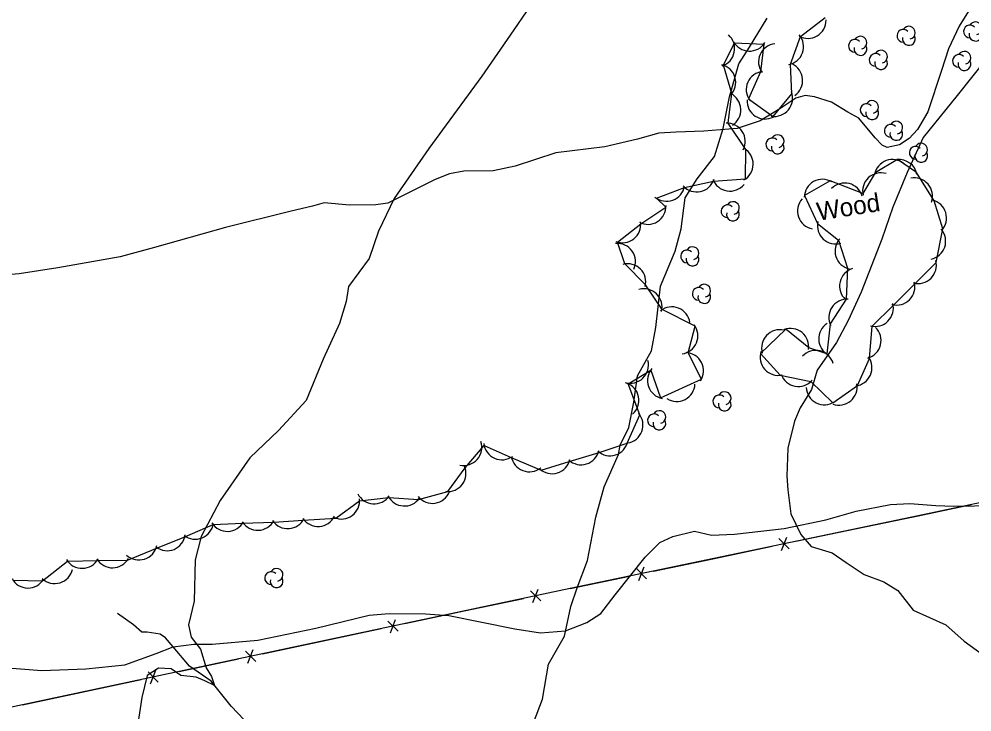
# Model space of a CAD drawing. Extents: x 643342 to 646936, y 5873857 to 5876103.
# Drawn here: x 645420.4 to 645577.3, y 5875713.3 to 5875827.4 of the extents above; entities that cross this region are included whole.
import ezdxf

# ---------------------------------------------------------------- set-up
doc = ezdxf.new("R2010")
doc.units = 0
for name, color, linetype in [('Niveau 2', 7, 'Continuous'), ('Niveau 22', 7, 'Continuous'), ('Niveau 37', 7, 'Continuous'), ('Niveau 4', 7, 'Continuous'), ('Niveau 44', 7, 'Continuous')]:
    doc.layers.add(name, color=color, linetype=linetype)

msp = doc.modelspace()

# ---------------------------------------------------------------- linework, layer by layer
at = {"layer": 'Niveau 2'}
for points in [[(645504.52, 5875829.46), (645501.28, 5875824.74), (645496.59, 5875817.97), (645487.87, 5875806.09), (645482.16, 5875797.83), (645479.59, 5875792.45), (645478.03, 5875787.96), (645474.65, 5875783.32), (645474.23, 5875780.85), (645473.18, 5875777.22), (645470.47, 5875771.36), (645467.68, 5875764.56), (645463.11, 5875759.64), (645458.39, 5875755.12), (645453.48, 5875748.08), (645450.38, 5875742.18), (645449.4, 5875738.32), (645449.2, 5875731.51), (645448.28, 5875727.6), (645448.75, 5875725.6), (645450.25, 5875723.58), (645451.22, 5875720.53), (645452.06, 5875719.12), (645452.59, 5875717.64), (645450.99, 5875718.4), (645449.53, 5875719), (645447.02, 5875719.28), (645445.42, 5875720.39), (645443.34, 5875720.45), (645441.49, 5875719.24), (645440.6, 5875715.62), (645439.95, 5875711.33)], [(645503.62, 5875707.59), (645506.6, 5875715.38), (645507.58, 5875721.14), (645510.21, 5875725.77), (645511.27, 5875730.61), (645512.31, 5875733.72), (645513.98, 5875738.2), (645515.35, 5875745.33), (645516.75, 5875750.32), (645519.08, 5875755.67), (645519.35, 5875757.2), (645520.81, 5875760.11), (645521.64, 5875764.29), (645522.23, 5875768.62), (645524.5, 5875772.76), (645525.25, 5875776.58), (645526.02, 5875783.37), (645528.43, 5875789.13), (645529.42, 5875792.81), (645530.05, 5875797.95), (645532.07, 5875801.08), (645534.9, 5875804.73), (645536.32, 5875809.37), (645537.35, 5875814.55), (645538.93, 5875820.01), (645540.69, 5875822.76), (645543.59, 5875827.52)], [(645580.21, 5875821.57), (645574.87, 5875814.77), (645569.25, 5875807.88), (645566.62, 5875802.11), (645564.26, 5875796.42), (645562.45, 5875791.13), (645559.05, 5875782.4), (645556.89, 5875777.71), (645554.98, 5875774.14), (645551.78, 5875769.53), (645550.86, 5875766.39), (645549.01, 5875763.34), (645548.06, 5875761.18), (645546.97, 5875756.69), (645546.81, 5875752.11), (645546.96, 5875749.87), (645547.48, 5875745.92), (645549.11, 5875742.48), (645550.83, 5875740.49), (645554.3, 5875739.46), (645556.57, 5875737.86), (645559.55, 5875735.92), (645562.81, 5875734.69), (645565.11, 5875733.27), (645567.64, 5875730.02), (645573.01, 5875727.59), (645576, 5875724.9), (645580.59, 5875721.6)]]:
    msp.add_lwpolyline(points, dxfattribs=at)
at = {"layer": 'Niveau 22'}
for points in [[(645577.57, 5875829.99), (645575.16, 5875826.21), (645573.44, 5875822.48), (645572.27, 5875818.91), (645570.01, 5875812.13), (645568.33, 5875809.22), (645566.97, 5875807.72), (645565.35, 5875806.65), (645563.32, 5875806.25), (645562.49, 5875806.64), (645561.35, 5875807.82), (645558.65, 5875811.06), (645556.84, 5875812.06), (645554.18, 5875813.69), (645551.34, 5875814.6), (645549.83, 5875814.82), (645548.27, 5875814.34), (645545.67, 5875812.62), (645542.41, 5875810.61), (645538.62, 5875809.36), (645533.15, 5875808.9), (645528.58, 5875808.74), (645525.72, 5875808.61), (645522.24, 5875807.63), (645516.84, 5875806.36), (645508.77, 5875805.33), (645502.07, 5875803.14), (645498.46, 5875802.37), (645493.63, 5875802.31), (645491.26, 5875801.87), (645488.92, 5875800.98), (645481.09, 5875797.07), (645479.16, 5875796.79), (645474.79, 5875796.76), (645470.61, 5875797.11), (645468.69, 5875796.59), (645465.2, 5875795.72), (645454.37, 5875793.06), (645442.67, 5875789.74), (645437.03, 5875788.22), (645426.8, 5875786.42), (645420.43, 5875785.41), (645414.01, 5875784.87)], [(645416.36, 5875720.7), (645424.15, 5875720.09), (645431.39, 5875720.37), (645437.8, 5875721.03), (645442.94, 5875722.87), (645445.76, 5875723.99), (645449.18, 5875724.4), (645452.18, 5875724.42), (645459.73, 5875725.07), (645469.23, 5875727.04), (645478.02, 5875729.19), (645481.33, 5875729.47), (645487.32, 5875729.41), (645491.14, 5875729.16), (645502.03, 5875726.96), (645506.23, 5875726.28), (645510.34, 5875726.63), (645513.9, 5875727.98), (645516.18, 5875729.45), (645518.54, 5875732.54), (645523.5, 5875738.76), (645525.92, 5875741.17), (645528.02, 5875742.16), (645531.61, 5875743.04), (645534.42, 5875742.36), (645538.19, 5875742.57), (645546.36, 5875743.5), (645553.23, 5875744.89), (645558.25, 5875746.36), (645563.88, 5875747.42), (645567.07, 5875747.58), (645571.34, 5875747.25), (645574.32, 5875747.16), (645581.18, 5875747.29)]]:
    msp.add_lwpolyline(points, dxfattribs=at)
at = {"layer": 'Niveau 37'}
for p, q in [((645656.81, 5875764.27), (645567.42, 5875745.36)), ((645567.42, 5875745.36), (645511.15, 5875733.6)), ((645511.15, 5875733.6), (645446.76, 5875719.92)), ((645446.76, 5875719.92), (645383.77, 5875706.55))]:
    msp.add_line(p, q, dxfattribs=at)
for points in [[(645567.42, 5875745.36), (645577.2, 5875747.43)], [(645558.09, 5875743.41), (645567.86, 5875745.45)], [(645548.31, 5875741.37), (645558.09, 5875743.41)], [(645545.52, 5875741.81), (645547.2, 5875740.11)], [(645545.93, 5875739.85), (645546.79, 5875742.07)], [(645534.62, 5875738.5), (645544.39, 5875740.55)], [(645524.84, 5875736.46), (645534.62, 5875738.5)], [(645522.05, 5875736.9), (645523.73, 5875735.21)], [(645522.46, 5875734.94), (645523.32, 5875737.17)], [(645511.15, 5875733.6), (645520.93, 5875735.64)], [(645504.6, 5875733.23), (645506.28, 5875731.54)], [(645505.01, 5875731.27), (645505.87, 5875733.5)], [(645493.7, 5875729.89), (645503.47, 5875731.97)], [(645483.92, 5875727.81), (645493.7, 5875729.89)], [(645481.13, 5875728.24), (645482.81, 5875726.56)], [(645481.54, 5875726.29), (645482.4, 5875728.51)], [(645470.23, 5875724.91), (645480.01, 5875726.98)], [(645460.45, 5875722.83), (645470.23, 5875724.91)], [(645457.66, 5875723.26), (645459.35, 5875721.57)], [(645458.07, 5875721.3), (645458.93, 5875723.53)], [(645446.76, 5875719.92), (645456.54, 5875722)], [(645441.63, 5875719.85), (645443.32, 5875718.17)], [(645442.04, 5875717.9), (645442.9, 5875720.12)], [(645430.72, 5875716.52), (645440.51, 5875718.59)], [(645420.94, 5875714.44), (645430.72, 5875716.52)]]:
    msp.add_lwpolyline(points, dxfattribs=at)
at = {"layer": 'Niveau 4'}
msp.add_lwpolyline([(645457.45, 5875711.96), (645455.29, 5875714.21), (645452.03, 5875718.35), (645448.47, 5875720.83), (645445.76, 5875723.99), (645444.48, 5875725.48), (645443.62, 5875726.1), (645441.51, 5875726.39), (645440.59, 5875726.43), (645439.21, 5875727.59), (645436.62, 5875729.46)], dxfattribs=at)
at = {"layer": 'Niveau 44'}
for points in [[(645537.13, 5875810.23), (645537.77, 5875815.12), (645536.4, 5875819.77), (645538.17, 5875823.45), (645543.02, 5875823.25), (645542.49, 5875818.69), (645540.52, 5875814.26), (645544.57, 5875811.35), (645547.66, 5875815.09), (645547.42, 5875819.97), (645549.04, 5875824.54), (645553.14, 5875827.65)], [(645419.4, 5875734.95), (645424.25, 5875734.86), (645428.38, 5875738.12), (645433.38, 5875738.2), (645438.23, 5875738.27), (645443.19, 5875740.27), (645447.68, 5875742.11), (645452.33, 5875744.15), (645457.18, 5875744.33), (645462.33, 5875744.52), (645467.18, 5875744.87), (645472.55, 5875745.18), (645476.46, 5875748.06), (645481.29, 5875748.59), (645486.14, 5875748.25), (645490.97, 5875749.55), (645493.84, 5875753.47), (645496.97, 5875757.17), (645501.4, 5875755.19), (645506.35, 5875753.1), (645510.99, 5875754.53), (645515.92, 5875756.01), (645520.53, 5875757.53), (645522.62, 5875762.18), (645520.71, 5875767.31), (645524.41, 5875769.57), (645526, 5875764.98), (645532.76, 5875768.09), (645530.55, 5875772.42), (645531.71, 5875776.79), (645526.27, 5875779.53), (645523.56, 5875783.62), (645520.12, 5875787.05), (645518.95, 5875790.66), (645522.76, 5875793.66), (645526.91, 5875796.4), (645525.34, 5875797.89), (645529.97, 5875799.67), (645534.72, 5875800.7), (645540, 5875801.05), (645540.07, 5875805.9), (645537.13, 5875810.23)], [(645550.42, 5875773.25), (645546.67, 5875776.33), (645542.47, 5875772.32), (645545.72, 5875768.72), (645550.76, 5875767.68), (645554.37, 5875764.19), (645558.47, 5875767.03), (645560.41, 5875771.48), (645560.87, 5875776.8), (645564.31, 5875780.22), (645567.96, 5875783.85), (645571.4, 5875787.28), (645572.5, 5875792.82), (645571.08, 5875797.46), (645568.17, 5875802.11), (645565.05, 5875804.24), (645561.33, 5875802.08), (645559.32, 5875798.66), (645553.95, 5875800.72), (645549.71, 5875798.35), (645551.88, 5875793.7), (645555.33, 5875790.96), (645556.79, 5875786.33), (645556.59, 5875781.24), (645553.92, 5875777.18), (645553.4, 5875772.22), (645550.42, 5875773.25)]]:
    msp.add_lwpolyline(points, dxfattribs=at)
for centre, radius, start, end in [((645550.28, 5875827.2), 3, 240.8205, 0.7984), ((645550.28, 5875827.2), 3, 240.8205, 0.7984), ((645550.28, 5875827.2), 3, 240.8205, 0.7984), ((645576.97, 5875825.33), 1.05, 44.1154, 269.804), ((645577.87, 5875825.86), 1.05, 282.2692, 149.7263), ((645535.22, 5875822.53), 3, 288.1566, 48.1346), ((645535.22, 5875822.53), 3, 288.1566, 48.1346), ((645535.22, 5875822.53), 3, 288.1566, 48.1346), ((645546.57, 5875822.84), 3, 280.5154, 40.4933), ((645546.57, 5875822.84), 3, 280.5154, 40.4933), ((645546.57, 5875822.84), 3, 280.5154, 40.4933), ((645566, 5875824.62), 1.05, 44.1154, 269.804), ((645566.9, 5875825.15), 1.05, 282.2692, 149.7263), ((645577.87, 5875824.81), 1.05, 166.9369, 29.6212), ((645540.67, 5875825.11), 3, 207.668, 327.6459), ((645540.67, 5875825.11), 3, 207.668, 327.6459), ((645540.67, 5875825.11), 3, 207.668, 327.6459), ((645545.15, 5875820.33), 3, 96.0461, 216.024), ((645545.15, 5875820.33), 3, 96.0461, 216.024), ((645545.15, 5875820.33), 3, 96.0461, 216.024), ((645558.03, 5875822.97), 1.05, 44.1154, 269.804), ((645558.93, 5875823.5), 1.05, 282.2692, 149.7263), ((645566.9, 5875824.1), 1.05, 166.9369, 29.6212), ((645558.93, 5875822.45), 1.05, 166.9369, 29.6212), ((645561.42, 5875820.66), 1.05, 44.1154, 269.804), ((645562.32, 5875821.19), 1.05, 282.2692, 149.7263), ((645576.05, 5875821.02), 1.05, 282.2692, 149.7263), ((645562.32, 5875820.14), 1.05, 166.9369, 29.6212), ((645575.15, 5875820.49), 1.05, 44.1154, 269.804), ((645576.05, 5875819.97), 1.05, 166.9369, 29.6212), ((645535.39, 5875816.95), 3, 316.3377, 76.3156), ((645535.39, 5875816.95), 3, 316.3377, 76.3156), ((645535.39, 5875816.95), 3, 316.3377, 76.3156), ((645543.12, 5875815.76), 3, 96.0461, 216.024), ((645543.12, 5875815.76), 3, 96.0461, 216.024), ((645543.12, 5875815.76), 3, 96.0461, 216.024), ((645546.42, 5875817.27), 3, 305.1398, 65.1177), ((645546.42, 5875817.27), 3, 305.1398, 65.1177), ((645546.42, 5875817.27), 3, 305.1398, 65.1177), ((645544.76, 5875814.35), 3, 260.3791, 20.3571), ((645544.76, 5875814.35), 3, 260.3791, 20.3571), ((645544.76, 5875814.35), 3, 260.3791, 20.3571), ((645536.24, 5875812.42), 3, 302.7735, 62.7515), ((645536.24, 5875812.42), 3, 302.7735, 62.7515), ((645536.24, 5875812.42), 3, 302.7735, 62.7515), ((645543.25, 5875813.92), 3, 177.1406, 297.1186), ((645543.25, 5875813.92), 3, 177.1406, 297.1186), ((645543.25, 5875813.92), 3, 177.1406, 297.1186), ((645560.86, 5875812.92), 1.05, 282.2692, 149.7263), ((645559.96, 5875812.39), 1.05, 44.1154, 269.804), ((645560.86, 5875811.87), 1.05, 166.9369, 29.6212), ((645536.96, 5875807.24), 3, 332.8523, 92.8302), ((645536.96, 5875807.24), 3, 332.8523, 92.8302), ((645536.96, 5875807.24), 3, 332.8523, 92.8302), ((645563.93, 5875808.98), 1.05, 44.1154, 269.804), ((645564.83, 5875809.51), 1.05, 282.2692, 149.7263), ((645544.41, 5875806.75), 1.05, 44.1154, 269.804), ((645545.31, 5875807.28), 1.05, 282.2692, 149.7263), ((645564.83, 5875808.46), 1.05, 166.9369, 29.6212), ((645538.27, 5875803.5), 3, 299.1809, 59.1588), ((645538.27, 5875803.5), 3, 299.1809, 59.1588), ((645538.27, 5875803.5), 3, 299.1809, 59.1588), ((645545.31, 5875806.23), 1.05, 166.9369, 29.6212), ((645568.03, 5875805.36), 1.05, 44.1154, 269.804), ((645568.93, 5875805.89), 1.05, 282.2692, 149.7263), ((645568.93, 5875804.84), 1.05, 166.9369, 29.6212), ((645564.21, 5875801.25), 3, 50.0669, 170.0449), ((645564.21, 5875801.25), 3, 50.0669, 170.0449), ((645564.21, 5875801.25), 3, 50.0669, 170.0449), ((645565.29, 5875801.25), 3, 10.616, 96.7417), ((645565.29, 5875801.25), 3, 10.616, 96.7417), ((645565.29, 5875801.25), 3, 10.616, 96.7417), ((645562.29, 5875799.05), 3, 73.3779, 193.3558), ((645562.29, 5875799.05), 3, 73.3779, 193.3558), ((645562.29, 5875799.05), 3, 73.3779, 193.3558), ((645567.8, 5875798.22), 3, 341.1335, 101.1114), ((645567.8, 5875798.22), 3, 341.1335, 101.1114), ((645567.8, 5875798.22), 3, 341.1335, 101.1114), ((645527, 5875800.38), 3, 230.2718, 350.2498), ((645527, 5875800.38), 3, 230.2718, 350.2498), ((645527, 5875800.38), 3, 230.2718, 350.2498), ((645531.97, 5875801.91), 3, 222.2419, 342.2198), ((645531.97, 5875801.91), 3, 222.2419, 342.2198), ((645531.97, 5875801.91), 3, 222.2419, 342.2198), ((645537.44, 5875802.05), 3, 200.7234, 320.7013), ((645537.44, 5875802.05), 3, 200.7234, 320.7013), ((645537.44, 5875802.05), 3, 200.7234, 320.7013), ((645552.69, 5875797.99), 3, 59.201, 179.179), ((645552.69, 5875797.99), 3, 59.201, 179.179), ((645552.69, 5875797.99), 3, 59.201, 179.179), ((645556.34, 5875797.38), 3, 15.9083, 135.8863), ((645556.34, 5875797.38), 3, 15.9083, 135.8863), ((645556.34, 5875797.38), 3, 15.9083, 135.8863), ((645523.92, 5875796.57), 3, 242.6115, 2.5895), ((645523.92, 5875796.57), 3, 242.6115, 2.5895), ((645523.92, 5875796.57), 3, 242.6115, 2.5895), ((645537.04, 5875795.73), 1.05, 44.1154, 269.804), ((645537.94, 5875796.26), 1.05, 282.2692, 149.7263), ((645551.58, 5875795.77), 3, 138.5965, 258.5744), ((645551.58, 5875795.77), 3, 138.5965, 258.5744), ((645551.58, 5875795.77), 3, 138.5965, 258.5744), ((645570.11, 5875794.62), 3, 317.0834, 77.0614), ((645570.11, 5875794.62), 3, 317.0834, 77.0614), ((645570.11, 5875794.62), 3, 317.0834, 77.0614), ((645537.94, 5875795.21), 1.05, 166.9369, 29.6212), ((645519.76, 5875793.55), 3, 248.1528, 8.1308), ((645519.76, 5875793.55), 3, 248.1528, 8.1308), ((645519.76, 5875793.55), 3, 248.1528, 8.1308), ((645554.85, 5875793.34), 3, 166.9551, 286.9331), ((645554.85, 5875793.34), 3, 166.9551, 286.9331), ((645554.85, 5875793.34), 3, 166.9551, 286.9331), ((645569.97, 5875790.8), 3, 281.1404, 41.1184), ((645569.97, 5875790.8), 3, 281.1404, 41.1184), ((645569.97, 5875790.8), 3, 281.1404, 41.1184), ((645518.89, 5875787.43), 3, 335.1064, 95.0843), ((645518.89, 5875787.43), 3, 335.1064, 95.0843), ((645518.89, 5875787.43), 3, 335.1064, 95.0843), ((645557.74, 5875789.18), 3, 137.4938, 257.4717), ((645557.74, 5875789.18), 3, 137.4938, 257.4717), ((645557.74, 5875789.18), 3, 137.4938, 257.4717), ((645530.38, 5875788.3), 1.05, 44.1154, 269.804), ((645531.28, 5875788.83), 1.05, 282.2692, 149.7263), ((645520.59, 5875784.09), 3, 344.9855, 104.9634), ((645520.59, 5875784.09), 3, 344.9855, 104.9634), ((645520.59, 5875784.09), 3, 344.9855, 104.9634), ((645531.28, 5875787.78), 1.05, 166.9369, 29.6212), ((645568.43, 5875786.82), 3, 254.9709, 14.9489), ((645568.43, 5875786.82), 3, 254.9709, 14.9489), ((645568.43, 5875786.82), 3, 254.9709, 14.9489), ((645558.49, 5875783.41), 3, 107.0123, 226.9902), ((645558.49, 5875783.41), 3, 107.0123, 226.9902), ((645558.49, 5875783.41), 3, 107.0123, 226.9902), ((645564.89, 5875783.28), 3, 254.9709, 14.9489), ((645564.89, 5875783.28), 3, 254.9709, 14.9489), ((645564.89, 5875783.28), 3, 254.9709, 14.9489), ((645523.26, 5875779.97), 3, 345.3782, 105.3562), ((645523.26, 5875779.97), 3, 345.3782, 105.3562), ((645523.26, 5875779.97), 3, 345.3782, 105.3562), ((645532.31, 5875782.12), 1.05, 44.1154, 269.804), ((645533.21, 5875782.65), 1.05, 282.2692, 149.7263), ((645533.21, 5875781.6), 1.05, 166.9369, 29.6212), ((645556.73, 5875778.24), 3, 86.6769, 206.6548), ((645556.73, 5875778.24), 3, 86.6769, 206.6548), ((645556.73, 5875778.24), 3, 86.6769, 206.6548), ((645527.87, 5875776.99), 3, 8.164, 128.142), ((645527.87, 5875776.99), 3, 8.164, 128.142), ((645527.87, 5875776.99), 3, 8.164, 128.142), ((645561.35, 5875779.76), 3, 254.8335, 14.8114), ((645561.35, 5875779.76), 3, 254.8335, 14.8114), ((645561.35, 5875779.76), 3, 254.8335, 14.8114), ((645529.16, 5875775.21), 3, 277.7433, 37.7213), ((645529.16, 5875775.21), 3, 277.7433, 37.7213), ((645529.16, 5875775.21), 3, 277.7433, 37.7213), ((645545.65, 5875773.22), 3, 76.4565, 196.4345), ((645545.65, 5875773.22), 3, 76.4565, 196.4345), ((645545.65, 5875773.22), 3, 76.4565, 196.4345), ((645547.42, 5875773.43), 3, 350.6126, 110.5906), ((645547.42, 5875773.43), 3, 350.6126, 110.5906), ((645547.42, 5875773.43), 3, 350.6126, 110.5906), ((645555.05, 5875774.73), 3, 122.6511, 242.629), ((645555.05, 5875774.73), 3, 122.6511, 242.629), ((645555.05, 5875774.73), 3, 122.6511, 242.629), ((645559.33, 5875774.44), 3, 286.0028, 45.9808), ((645559.33, 5875774.44), 3, 286.0028, 45.9808), ((645559.33, 5875774.44), 3, 286.0028, 45.9808), ((645530.09, 5875769.45), 3, 327.0883, 87.0662), ((645530.09, 5875769.45), 3, 327.0883, 87.0662), ((645530.09, 5875769.45), 3, 327.0883, 87.0662), ((645545.41, 5875771.7), 3, 162.0278, 282.0057), ((645545.41, 5875771.7), 3, 162.0278, 282.0057), ((645545.41, 5875771.7), 3, 162.0278, 282.0057), ((645551.58, 5875769.81), 3, 16.4721, 136.45), ((645551.58, 5875769.81), 3, 16.4721, 136.45), ((645551.58, 5875769.81), 3, 16.4721, 136.45), ((645557.83, 5875769.96), 3, 276.3506, 36.3285), ((645557.83, 5875769.96), 3, 276.3506, 36.3285), ((645557.83, 5875769.96), 3, 276.3506, 36.3285), ((645521.03, 5875770.41), 3, 253.8969, 13.8749), ((645521.03, 5875770.41), 3, 253.8969, 13.8749), ((645521.03, 5875770.41), 3, 253.8969, 13.8749), ((645526.87, 5875767.85), 3, 139.038, 259.0159), ((645526.87, 5875767.85), 3, 139.038, 259.0159), ((645526.87, 5875767.85), 3, 139.038, 259.0159), ((645548.7, 5875769.86), 3, 199.4209, 319.3988), ((645548.7, 5875769.86), 3, 199.4209, 319.3988), ((645548.7, 5875769.86), 3, 199.4209, 319.3988), ((645519.45, 5875764.59), 3, 311.1519, 71.1299), ((645519.45, 5875764.59), 3, 311.1519, 71.1299), ((645519.45, 5875764.59), 3, 311.1519, 71.1299), ((645528.69, 5875767.41), 3, 237.2773, 357.2552), ((645528.69, 5875767.41), 3, 237.2773, 357.2552), ((645528.69, 5875767.41), 3, 237.2773, 357.2552), ((645553.01, 5875766.86), 3, 183.0254, 303.0033), ((645553.01, 5875766.86), 3, 183.0254, 303.0033), ((645553.01, 5875766.86), 3, 183.0254, 303.0033), ((645555.38, 5875766.79), 3, 250.4002, 10.3781), ((645555.38, 5875766.79), 3, 250.4002, 10.3781), ((645555.38, 5875766.79), 3, 250.4002, 10.3781), ((645535.68, 5875764.42), 1.05, 44.1154, 269.804), ((645536.58, 5875764.95), 1.05, 282.2692, 149.7263), ((645536.58, 5875763.9), 1.05, 166.9369, 29.6212), ((645520.12, 5875760.52), 3, 279.7304, 39.7084), ((645520.12, 5875760.52), 3, 279.7304, 39.7084), ((645520.12, 5875760.52), 3, 279.7304, 39.7084), ((645524.92, 5875761.3), 1.05, 44.1154, 269.804), ((645525.82, 5875761.83), 1.05, 282.2692, 149.7263), ((645525.82, 5875760.78), 1.05, 166.9369, 29.6212), ((645493.6, 5875756.87), 3, 258.131, 18.109), ((645493.6, 5875756.87), 3, 258.131, 18.109), ((645493.6, 5875756.87), 3, 258.131, 18.109), ((645499.91, 5875757.79), 3, 185.9368, 305.9148), ((645499.91, 5875757.79), 3, 185.9368, 305.9148), ((645499.91, 5875757.79), 3, 185.9368, 305.9148), ((645517.68, 5875758.45), 3, 228.161, 348.1389), ((645517.68, 5875758.45), 3, 228.161, 348.1389), ((645517.68, 5875758.45), 3, 228.161, 348.1389), ((645512.93, 5875756.97), 3, 227.1112, 347.0892), ((645512.93, 5875756.97), 3, 227.1112, 347.0892), ((645512.93, 5875756.97), 3, 227.1112, 347.0892), ((645504.41, 5875755.82), 3, 189.0429, 309.0209), ((645504.41, 5875755.82), 3, 189.0429, 309.0209), ((645504.41, 5875755.82), 3, 189.0429, 309.0209), ((645508.15, 5875755.5), 3, 227.1112, 347.0892), ((645508.15, 5875755.5), 3, 227.1112, 347.0892), ((645508.15, 5875755.5), 3, 227.1112, 347.0892), ((645490.98, 5875752.55), 3, 263.8878, 23.8658), ((645490.98, 5875752.55), 3, 263.8878, 23.8658), ((645490.98, 5875752.55), 3, 263.8878, 23.8658), ((645488.46, 5875750.62), 3, 218.8408, 338.8187), ((645488.46, 5875750.62), 3, 218.8408, 338.8187), ((645488.46, 5875750.62), 3, 218.8408, 338.8187), ((645473.46, 5875748.04), 3, 246.4406, 6.4185), ((645473.46, 5875748.04), 3, 246.4406, 6.4185), ((645473.46, 5875748.04), 3, 246.4406, 6.4185), ((645478.85, 5875750.53), 3, 206.0186, 325.9966), ((645478.85, 5875750.53), 3, 206.0186, 325.9966), ((645478.85, 5875750.53), 3, 206.0186, 325.9966), ((645483.84, 5875750.18), 3, 206.0186, 325.9966), ((645483.84, 5875750.18), 3, 206.0186, 325.9966), ((645483.84, 5875750.18), 3, 206.0186, 325.9966), ((645459.69, 5875746.18), 3, 212.0939, 332.0719), ((645459.69, 5875746.18), 3, 212.0939, 332.0719), ((645459.69, 5875746.18), 3, 212.0939, 332.0719), ((645464.63, 5875746.45), 3, 214.0953, 334.0733), ((645464.63, 5875746.45), 3, 214.0953, 334.0733), ((645464.63, 5875746.45), 3, 214.0953, 334.0733), ((645469.62, 5875746.81), 3, 214.0953, 334.0733), ((645469.62, 5875746.81), 3, 214.0953, 334.0733), ((645469.62, 5875746.81), 3, 214.0953, 334.0733), ((645449.4, 5875744.71), 3, 232.2714, 352.2494), ((645449.4, 5875744.71), 3, 232.2714, 352.2494), ((645449.4, 5875744.71), 3, 232.2714, 352.2494), ((645454.69, 5875746), 3, 212.0939, 332.0719), ((645454.69, 5875746), 3, 212.0939, 332.0719), ((645454.69, 5875746), 3, 212.0939, 332.0719), ((645444.77, 5875742.82), 3, 232.2714, 352.2494), ((645444.77, 5875742.82), 3, 232.2714, 352.2494), ((645444.77, 5875742.82), 3, 232.2714, 352.2494), ((645440.13, 5875741.3), 3, 227.6243, 347.6022), ((645440.13, 5875741.3), 3, 227.6243, 347.6022), ((645440.13, 5875741.3), 3, 227.6243, 347.6022), ((645430.78, 5875739.92), 3, 210.9374, 330.9153), ((645430.78, 5875739.92), 3, 210.9374, 330.9153), ((645430.78, 5875739.92), 3, 210.9374, 330.9153), ((645435.78, 5875740), 3, 210.9374, 330.9153), ((645435.78, 5875740), 3, 210.9374, 330.9153), ((645435.78, 5875740), 3, 210.9374, 330.9153), ((645462.8, 5875735.84), 1.05, 282.2692, 149.7263), ((645426.26, 5875737.42), 3, 227.0997, 347.0776), ((645426.26, 5875737.42), 3, 227.0997, 347.0776), ((645426.26, 5875737.42), 3, 227.0997, 347.0776), ((645461.9, 5875735.31), 1.05, 44.1154, 269.804), ((645462.8, 5875734.79), 1.05, 166.9369, 29.6212), ((645421.86, 5875736.67), 3, 208.9071, 328.885), ((645421.86, 5875736.67), 3, 208.9071, 328.885), ((645421.86, 5875736.67), 3, 208.9071, 328.885)]:
    msp.add_arc(centre, radius, start, end, dxfattribs=at)

# ---------------------------------------------------------------- texts
msp.add_text('Wood', height=3, rotation=8.9405, dxfattribs=at).set_placement((645551.99, 5875794.16))

doc.saveas('drawing.dxf')
